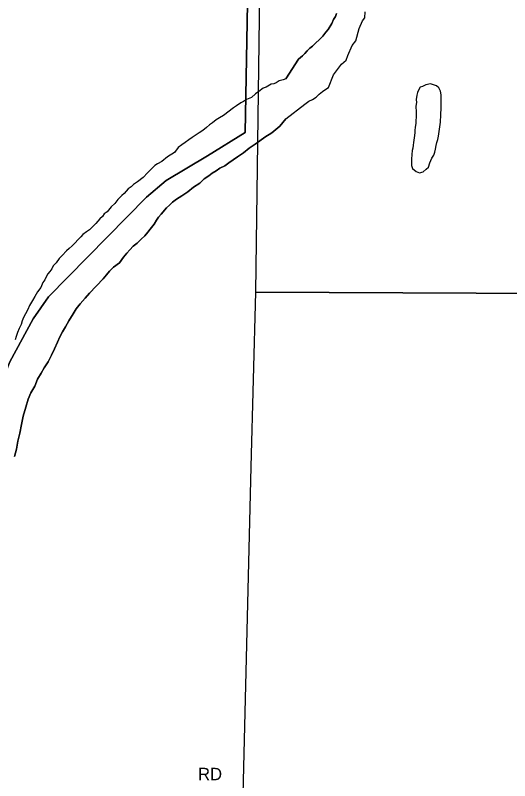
# Model space of a CAD drawing. Extents: x 2010165 to 2382125, y 1060529 to 1407316.
# Drawn here: x 2138947 to 2140939, y 1241658 to 1244739 of the extents above; entities that cross this region are included whole.
import ezdxf

# ---------------------------------------------------------------- set-up
doc = ezdxf.new("R2010")
doc.units = 0
for name, color, linetype in [('GM_X_City_Street_Text', 7, 'Continuous'), ('GM_X_Corporation', 7, 'Continuous'), ('GM_X_Major_River', 7, 'Continuous'), ('GM_X_Minor_Lake', 7, 'Continuous'), ('GM_X_Section', 7, 'Continuous')]:
    doc.layers.add(name, color=color, linetype=linetype)

msp = doc.modelspace()

# ---------------------------------------------------------------- linework, layer by layer
at = {"layer": 'GM_X_Corporation'}
for points in [[(2137615.4, 1241310.6), (2137621.9, 1242203.2), (2137917, 1242034), (2138135.6, 1241938.8), (2138263.9, 1241901.3), (2138358.1, 1241899.7), (2138414.1, 1241910), (2138500.1, 1241950.5), (2138575.9, 1242011), (2138623.7, 1242085.5), (2138669.2, 1242238.1), (2138748, 1242571.4), (2138802.7, 1242922.6), (2138832.2, 1243055.1), (2138873.6, 1243217.8), (2138925.2, 1243344.4), (2139018.7, 1243517.3), (2139080.4, 1243605.8), (2139475.4, 1244006.8), (2139555.2, 1244073.3), (2139721.1, 1244172.4), (2139872.9, 1244267.3), (2139898.6, 1245676.5)], [(2139898.6, 1245676.5), (2139872.9, 1244267.3), (2139721.1, 1244172.4), (2139555.2, 1244073.3), (2139475.4, 1244006.8), (2139080.4, 1243605.8), (2139018.7, 1243517.3), (2138925.2, 1243344.4), (2138873.6, 1243217.8), (2138832.2, 1243055.1), (2138802.7, 1242922.6), (2138748, 1242571.4), (2138669.2, 1242238.1), (2138623.7, 1242085.5), (2138575.9, 1242011), (2138500.1, 1241950.5), (2138414.1, 1241910), (2138358.1, 1241899.7), (2138263.9, 1241901.3), (2138135.6, 1241938.8), (2137917, 1242034), (2137621.9, 1242203.2), (2137615.4, 1241310.6)]]:
    msp.add_lwpolyline(points, dxfattribs=at)
at = {"layer": 'GM_X_Major_River'}
for points in [[(2140036.4, 1244482.6), (2140087.9, 1244562.6), (2140103.7, 1244574.9), (2140113.6, 1244585.2), (2140123.4, 1244595.4), (2140133.3, 1244605.6), (2140145.1, 1244613.9), (2140157, 1244626.1), (2140172.7, 1244640.5), (2140186.5, 1244654.8), (2140198.3, 1244671.1), (2140208.1, 1244681.3), (2140221.7, 1244705.6), (2140229.4, 1244721.9), (2140237.2, 1244734), (2140241, 1244746.2)], [(2140241, 1244746.2), (2140237.2, 1244734), (2140229.4, 1244721.9), (2140221.7, 1244705.6), (2140208.1, 1244681.3), (2140198.3, 1244671.1), (2140186.5, 1244654.8), (2140172.7, 1244640.5), (2140157, 1244626.1), (2140145.1, 1244613.9), (2140133.3, 1244605.6), (2140123.4, 1244595.4), (2140113.6, 1244585.2), (2140103.7, 1244574.9), (2140087.9, 1244562.6), (2140036.4, 1244482.6)], [(2140037.5, 1244321.9), (2140113.4, 1244380.5), (2140129.2, 1244392.8), (2140145.1, 1244399.1), (2140159, 1244409.4), (2140170.8, 1244421.7), (2140184.6, 1244432), (2140194.6, 1244438.2), (2140208.4, 1244448.5), (2140229.6, 1244499.1), (2140260.9, 1244541.8), (2140280.6, 1244558.3), (2140286.3, 1244576.4), (2140303.6, 1244616.9), (2140319.3, 1244635.3), (2140332.4, 1244685.7), (2140345.9, 1244716.1), (2140355.7, 1244728.3), (2140357.3, 1244752.4)], [(2140037.5, 1244321.9), (2140113.4, 1244380.5), (2140129.2, 1244392.8), (2140145.1, 1244399.1), (2140159, 1244409.4), (2140170.8, 1244421.7), (2140184.6, 1244432), (2140194.6, 1244438.2), (2140208.4, 1244448.5), (2140229.6, 1244499.1), (2140260.9, 1244541.8), (2140280.6, 1244558.3), (2140286.3, 1244576.4), (2140303.6, 1244616.9), (2140319.3, 1244635.3), (2140332.4, 1244685.7), (2140345.9, 1244716.1), (2140355.7, 1244728.3), (2140357.3, 1244752.4)], [(2140036.4, 1244482.6), (2140026.3, 1244479), (2140010.3, 1244474.9), (2139998.3, 1244466.8), (2139988.3, 1244462.8), (2139978.2, 1244460.8), (2139958.2, 1244448.7), (2139946.2, 1244444.6), (2139928.2, 1244432.5), (2139914.2, 1244422.4), (2139898.2, 1244408.3), (2139878.1, 1244400.2), (2139866.1, 1244392.2), (2139856.1, 1244386.1), (2139838.1, 1244374), (2139826.1, 1244366), (2139786, 1244335.7), (2139770, 1244325.7), (2139756, 1244317.6), (2139742, 1244305.5), (2139730, 1244297.4), (2139718, 1244287.4), (2139702, 1244275.3), (2139687.9, 1244265.2), (2139671.9, 1244255.1), (2139659.9, 1244247.1), (2139645.9, 1244237), (2139631.9, 1244226.9), (2139617.9, 1244216.8), (2139603.9, 1244206.8), (2139587.9, 1244186.6), (2139559.9, 1244168.5), (2139537.9, 1244150.3), (2139519.8, 1244140.3), (2139509.8, 1244134.2), (2139489.8, 1244114.1), (2139479.8, 1244104), (2139461.8, 1244085.9), (2139439.8, 1244067.8), (2139423.8, 1244057.7), (2139413.8, 1244047.6), (2139401.8, 1244039.6), (2139385.8, 1244021.4), (2139375.8, 1244013.4), (2139359.8, 1243997.3), (2139347.8, 1243981.2), (2139333.8, 1243967.1), (2139317.8, 1243947), (2139305.8, 1243938.9), (2139297.8, 1243928.9), (2139287.8, 1243918.8), (2139271.8, 1243900.7), (2139255.8, 1243884.6), (2139245.8, 1243874.5), (2139233.8, 1243866.4), (2139219.8, 1243856.4), (2139211.8, 1243846.3), (2139175.8, 1243810.1), (2139163.8, 1243800), (2139153.8, 1243789.9), (2139135.8, 1243771.8), (2139123.8, 1243759.8), (2139111.8, 1243741.6), (2139099.8, 1243729.6), (2139093.9, 1243717.5), (2139085.9, 1243707.4), (2139077.9, 1243697.4), (2139071.9, 1243685.3), (2139065.9, 1243673.3), (2139057.9, 1243663.2), (2139050, 1243643.1), (2139036, 1243625), (2139026, 1243606.9), (2139016, 1243590.8), (2139004.1, 1243570.7), (2138998.1, 1243554.7), (2138988.1, 1243536.6), (2138980.2, 1243522.5), (2138974.2, 1243508.4), (2138970.2, 1243494.4), (2138962.2, 1243478.3), (2138956.3, 1243462.2), (2138950.3, 1243446.1), (2138946.3, 1243432.1)], [(2140036.4, 1244482.6), (2140026.3, 1244479), (2140010.3, 1244474.9), (2139998.3, 1244466.8), (2139988.3, 1244462.8), (2139978.2, 1244460.8), (2139958.2, 1244448.7), (2139946.2, 1244444.6), (2139928.2, 1244432.5), (2139914.2, 1244422.4), (2139898.2, 1244408.3), (2139878.1, 1244400.2), (2139866.1, 1244392.2), (2139856.1, 1244386.1), (2139838.1, 1244374), (2139826.1, 1244366), (2139786, 1244335.7), (2139770, 1244325.7), (2139756, 1244317.6), (2139742, 1244305.5), (2139730, 1244297.4), (2139718, 1244287.4), (2139702, 1244275.3), (2139687.9, 1244265.2), (2139671.9, 1244255.1), (2139659.9, 1244247.1), (2139645.9, 1244237), (2139631.9, 1244226.9), (2139617.9, 1244216.8), (2139603.9, 1244206.8), (2139587.9, 1244186.6), (2139559.9, 1244168.5), (2139537.9, 1244150.3), (2139519.8, 1244140.3), (2139509.8, 1244134.2), (2139489.8, 1244114.1), (2139479.8, 1244104), (2139461.8, 1244085.9), (2139439.8, 1244067.8), (2139423.8, 1244057.7), (2139413.8, 1244047.6), (2139401.8, 1244039.6), (2139385.8, 1244021.4), (2139375.8, 1244013.4), (2139359.8, 1243997.3), (2139347.8, 1243981.2), (2139333.8, 1243967.1), (2139317.8, 1243947), (2139305.8, 1243938.9), (2139297.8, 1243928.9), (2139287.8, 1243918.8), (2139271.8, 1243900.7), (2139255.8, 1243884.6), (2139245.8, 1243874.5), (2139233.8, 1243866.4), (2139219.8, 1243856.4), (2139211.8, 1243846.3), (2139175.8, 1243810.1), (2139163.8, 1243800), (2139153.8, 1243789.9), (2139135.8, 1243771.8), (2139123.8, 1243759.8), (2139111.8, 1243741.6), (2139099.8, 1243729.6), (2139093.9, 1243717.5), (2139085.9, 1243707.4), (2139077.9, 1243697.4), (2139071.9, 1243685.3), (2139065.9, 1243673.3), (2139057.9, 1243663.2), (2139050, 1243643.1), (2139036, 1243625), (2139026, 1243606.9), (2139016, 1243590.8), (2139004.1, 1243570.7), (2138998.1, 1243554.7), (2138988.1, 1243536.6), (2138980.2, 1243522.5), (2138974.2, 1243508.4), (2138970.2, 1243494.4), (2138962.2, 1243478.3), (2138956.3, 1243462.2), (2138950.3, 1243446.1), (2138946.3, 1243432.1)], [(2140037.5, 1244321.9), (2140012.9, 1244292.3), (2139980.9, 1244266.1), (2139952.9, 1244248), (2139932.9, 1244233.9), (2139912.9, 1244219.8), (2139888.8, 1244203.6), (2139866.8, 1244185.5), (2139842.8, 1244169.4), (2139824.8, 1244157.3), (2139806.8, 1244145.2), (2139790.7, 1244133.1), (2139770.7, 1244123), (2139756.7, 1244112.9), (2139740.7, 1244102.8), (2139726.7, 1244092.7), (2139708.7, 1244080.6), (2139690.7, 1244062.5), (2139664.6, 1244046.4), (2139642.6, 1244028.3), (2139618.6, 1244012.1), (2139596.6, 1243998), (2139580.6, 1243985.9), (2139568.6, 1243973.9), (2139556.6, 1243963.8), (2139534.6, 1243937.6), (2139524.6, 1243925.6), (2139516.6, 1243913.5), (2139506.6, 1243897.4), (2139490.6, 1243877.3), (2139480.6, 1243865.2), (2139468.6, 1243851.1), (2139454.7, 1243837), (2139438.7, 1243820.9), (2139422.6, 1243808.8), (2139408.6, 1243794.8), (2139396.6, 1243780.7), (2139382.7, 1243764.6), (2139366.7, 1243742.4), (2139342.7, 1243724.3), (2139326.7, 1243708.2), (2139314.7, 1243694.1), (2139300.7, 1243678), (2139246.7, 1243619.7), (2139228.7, 1243599.5), (2139208.7, 1243577.4), (2139192.7, 1243557.3), (2139180.8, 1243537.2), (2139162.8, 1243509), (2139148.8, 1243484.9), (2139136.9, 1243464.8), (2139126.9, 1243444.7), (2139116.9, 1243422.6), (2139105, 1243396.5), (2139093.1, 1243370.3), (2139079.1, 1243344.2), (2139063.1, 1243320.1), (2139051.2, 1243298), (2139037.2, 1243273.8), (2139025.2, 1243245.7), (2139009.3, 1243219.6), (2138999.4, 1243193.5), (2138989.4, 1243161.3), (2138979.5, 1243125.2), (2138971.6, 1243091.1), (2138965.7, 1243056.9), (2138957.8, 1243024.8), (2138951.9, 1242992.7), (2138943.9, 1242962.5)], [(2138943.9, 1242962.5), (2138951.9, 1242992.7), (2138957.8, 1243024.8), (2138965.7, 1243056.9), (2138971.6, 1243091.1), (2138979.5, 1243125.2), (2138989.4, 1243161.3), (2138999.4, 1243193.5), (2139009.3, 1243219.6), (2139025.2, 1243245.7), (2139037.2, 1243273.8), (2139051.2, 1243298), (2139063.1, 1243320.1), (2139079.1, 1243344.2), (2139093.1, 1243370.3), (2139105, 1243396.5), (2139116.9, 1243422.6), (2139126.9, 1243444.7), (2139136.9, 1243464.8), (2139148.8, 1243484.9), (2139162.8, 1243509), (2139180.8, 1243537.2), (2139192.7, 1243557.3), (2139208.7, 1243577.4), (2139228.7, 1243599.5), (2139246.7, 1243619.7), (2139300.7, 1243678), (2139314.7, 1243694.1), (2139326.7, 1243708.2), (2139342.7, 1243724.3), (2139366.7, 1243742.4), (2139382.7, 1243764.6), (2139396.6, 1243780.7), (2139408.6, 1243794.8), (2139422.6, 1243808.8), (2139438.7, 1243820.9), (2139454.7, 1243837), (2139468.6, 1243851.1), (2139480.6, 1243865.2), (2139490.6, 1243877.3), (2139506.6, 1243897.4), (2139516.6, 1243913.5), (2139524.6, 1243925.6), (2139534.6, 1243937.6), (2139556.6, 1243963.8), (2139568.6, 1243973.9), (2139580.6, 1243985.9), (2139596.6, 1243998), (2139618.6, 1244012.1), (2139642.6, 1244028.3), (2139664.6, 1244046.4), (2139690.7, 1244062.5), (2139708.7, 1244080.6), (2139726.7, 1244092.7), (2139740.7, 1244102.8), (2139756.7, 1244112.9), (2139770.7, 1244123), (2139790.7, 1244133.1), (2139806.8, 1244145.2), (2139824.8, 1244157.3), (2139842.8, 1244169.4), (2139866.8, 1244185.5), (2139888.8, 1244203.6), (2139912.9, 1244219.8), (2139932.9, 1244233.9), (2139952.9, 1244248), (2139980.9, 1244266.1), (2140012.9, 1244292.3), (2140037.5, 1244321.9)]]:
    msp.add_lwpolyline(points, dxfattribs=at)
at = {"layer": 'GM_X_Minor_Lake'}
for points in [[(2140619.6, 1244462.4), (2140601.6, 1244458.1), (2140587.6, 1244451.8), (2140577.6, 1244449.6), (2140571.8, 1244437.4), (2140568, 1244427.3), (2140564.2, 1244417.2), (2140562.5, 1244399.1), (2140562.8, 1244387.1), (2140561, 1244373), (2140561.5, 1244348.9), (2140561.8, 1244328.9), (2140560.1, 1244314.8), (2140560.3, 1244304.8), (2140558.6, 1244286.7), (2140556.8, 1244276.6), (2140557, 1244266.6), (2140555.2, 1244254.5), (2140551.7, 1244226.3), (2140549.9, 1244216.3), (2140548.1, 1244204.2), (2140546.3, 1244194.1), (2140544.6, 1244178), (2140542.9, 1244159.9), (2140543.1, 1244147.9), (2140543.4, 1244133.8), (2140547.6, 1244121.9), (2140561.9, 1244110.1), (2140576, 1244104.4), (2140590, 1244108.7), (2140601.8, 1244118.9), (2140611.7, 1244127.1), (2140617.4, 1244145.3), (2140625.1, 1244163.5), (2140632.9, 1244175.7), (2140636.7, 1244187.8), (2140640.5, 1244199.9), (2140642.2, 1244214), (2140646, 1244226.1), (2140649.8, 1244238.2), (2140651.5, 1244252.3), (2140660.5, 1244308.6)], [(2140660.5, 1244308.6), (2140660.4, 1244314.7), (2140662.1, 1244330.8), (2140663.3, 1244373), (2140663.1, 1244385), (2140662.9, 1244399), (2140662.7, 1244409.1), (2140662.5, 1244419.1), (2140660.2, 1244433.1), (2140654, 1244447), (2140643.8, 1244454.9), (2140619.6, 1244462.4)]]:
    msp.add_lwpolyline(points, dxfattribs=at)
at = {"layer": 'GM_X_Section'}
for points in [[(2140054.4, 1246054.7), (2142054.5, 1246069.6), (2141988.6, 1243614.5), (2139915.9, 1243624.1), (2139948, 1246034.7)], [(2141988.6, 1243614.5), (2141922.4, 1241143.5), (2139854.6, 1241162.3), (2139897.2, 1242921.7), (2139915.9, 1243624.1)]]:
    msp.add_lwpolyline(points, close=True, dxfattribs=at)

# ---------------------------------------------------------------- texts
at = {"layer": 'GM_X_City_Street_Text'}
msp.add_text('RD', height=50, rotation=0, dxfattribs=at).set_placement((2139683.5, 1241659.8))

doc.saveas('drawing.dxf')
